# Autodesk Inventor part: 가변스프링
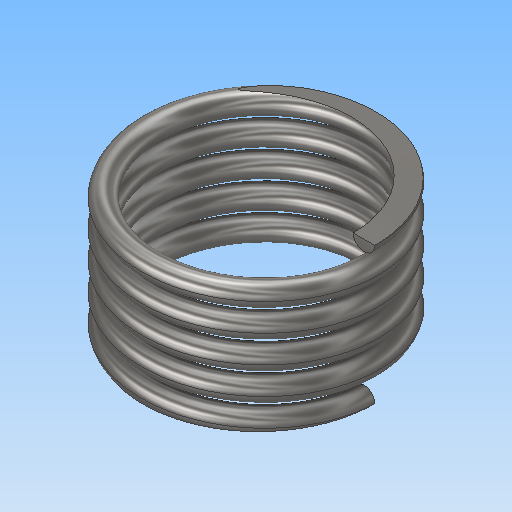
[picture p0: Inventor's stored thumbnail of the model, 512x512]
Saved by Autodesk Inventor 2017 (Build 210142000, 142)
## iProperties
Part Number: 가변스프링
Material: 스테인레스 스틸
Document SubType Name: Modeling
Designer: mrc
Mass: 7.63151 g
Surface Area: 19.5658 cm^2
Volume: 0.953939 cm^3
Density: 8 g/cm^3
Appearance: 반연마
Author: mrc
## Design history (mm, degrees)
sketch "스케치1"
  geometry: L1 (0, 0)-(0, 12.7); L2 (0, 12.7)-(10, 12.7); L3 (10, 12.7)-(10, 0); L4 (10, 0)-(0, 0); C1 r 1 at (10, 0)
  constraints: 8 end point, 3 perpendicular, 1 centre point, 1 coincident, 1 vertical
  dimensions: "d0" = 12.7 distance between parallel lines of L4 L2 (derived); "d1" = 20 diameter of L3 L1; "d2" = 2 diameter of C1
feature "코일1" sketch "스케치1" pitch "d3" = 10; turns "d5" = 5; dims "d4" = 12.7 (= d0), "d6" = 0, angle "d7" = 90 deg, angle "d8" = 90 deg, "d9" = 0, "d10" = 0
sketch "스케치2"
  geometry: L1 (12.7, 15.977)-(0, 15.977); L2 (0, 15.977)-(0, -15.977); L3 (0, -15.977)-(12.7, -15.977); L4 (12.7, -15.977)-(12.7, 15.977); 2 further points
  constraints: 8 end point, 2 midpoint, 2 parallel, 1 horizontal, 1 horizontal alignment, 1 perpendicular
  dimensions: "d11" = 31.95358 distance between parallel lines of L1 L3
extrude "돌출1" sketch "스케치2" stored distance "d12" = 0; taper "d13" = 0 deg
node "솔리드1"
